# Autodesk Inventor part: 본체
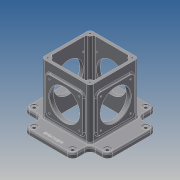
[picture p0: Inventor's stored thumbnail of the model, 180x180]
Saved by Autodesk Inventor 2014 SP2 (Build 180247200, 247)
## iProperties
Created: 2018-09
Part Number: 본체
Material: 알루미늄 6061
Document SubType Name: Modeling
Designer: mduedu
Density: 2.71 g/cm^3
Appearance: 기본값
Mass: 1126.64 g
Surface Area: 1144.86 cm^2
Volume: 415.735 cm^3
Author: mduedu
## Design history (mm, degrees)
sketch "스케치1"
  geometry: L1 (90, 52.5)-(-90, 52.5); L2 (-90, 52.5)-(-90, -52.5); L3 (-90, -52.5)-(90, -52.5); L4 (90, -52.5)-(90, 52.5); L5 (90, 52.5)-(-90, -52.5); L6 (-90, 52.5)-(90, -52.5); L7 (-52.5, -90)-(52.5, -90); L8 (52.5, -90)-(52.5, 90); L9 (52.5, 90)-(-52.5, 90); L10 (-52.5, 90)-(-52.5, -90); L11 (-52.5, -90)-(52.5, 90); L12 (52.5, -90)-(-52.5, 90); 1 further point
  constraints: 24 end point, 4 midpoint, 4 parallel, 2 horizontal, 2 perpendicular
  dimensions: "d0" = 180 distance of L3.end L2.end; "d1" = 105 distance of L2.end L1.end; "d105" = 105 distance of L9.end L8.end; "d106" = 180 distance of L8.end L7.end
extrude "돌출1" new body sketch "스케치1" distance "d2" = 10; taper "d3" = 0 deg
fillet "모깎기16" dims "d107" = 11
sketch "스케치2"
  geometry: L1 (-52.5, -52.5)-(52.5, -52.5); L2 (52.5, -52.5)-(52.5, 52.5); L3 (52.5, 52.5)-(-52.5, 52.5); L4 (-52.5, 52.5)-(-52.5, -52.5); L5 (-52.5, -52.5)-(52.5, 52.5); L6 (52.5, -52.5)-(-52.5, 52.5); 1 further point
  constraints: 12 end point, 2 midpoint, 2 parallel, 1 horizontal, 1 perpendicular
  dimensions: "d4" = 105 distance of L3.end L2.end; "d5" = 105 distance of L2.end L1.end
extrude "돌출2" join sketch "스케치2" distance "d6" = 110; taper "d7" = 0 deg
sketch "스케치14"
  geometry: L1 (-52.5, 52.5)-(52.5, 52.5) reference; L2 (52.5, 52.5)-(52.5, -52.5) reference; L3 (52.5, -52.5)-(-52.5, -52.5) reference; L4 (-52.5, -52.5)-(-52.5, 52.5) reference; L5 (46.5, 46.5)-(-46.5, 46.5); L6 (-46.5, 46.5)-(-46.5, -46.5); L7 (-46.5, -46.5)-(46.5, -46.5); L8 (46.5, -46.5)-(46.5, 46.5); 1 further point
  constraints: 8 end point, 3 other
  dimensions: "d85" = 6 distance between parallel lines of L5 L1
extrude "돌출10" cut sketch "스케치14" stored distance "d86" = 10; taper "d87" = 0 deg
fillet "모깎기1" dims "d12" = 7
sketch "스케치15"
  geometry: A1 r 7 centre (-45.5, 45.5) between (-45.5, 52.5) and (-52.5, 45.5) reference; A2 r 7 centre (45.5, 45.5) between (52.5, 45.5) and (45.5, 52.5) reference; A3 r 7 centre (45.5, -45.5) between (45.5, -52.5) and (52.5, -45.5) reference; A4 r 7 centre (-45.5, -45.5) between (-52.5, -45.5) and (-45.5, -52.5) reference; 5 further points
  constraints: 4 coincident, 4 vertical alignment, 8 other
extrude "돌출11" join sketch "스케치15" stored distance "d88" = 10; taper "d89" = 0 deg
fillet "모깎기15" dims "d90" = 3
sketch "스케치6"
  geometry: L1 (50, 20)-(130, 20); L2 (130, 20)-(130, 100); L3 (130, 100)-(50, 100); L4 (50, 100)-(50, 20); L5 (50, 20)-(130, 100); L6 (130, 20)-(50, 100); L7 (0, 0)-(180, 0) reference; 4 further points
  constraints: 12 end point, 4 midpoint, 2 parallel, 1 horizontal, 1 perpendicular, 1 vertical alignment
  dimensions: "d25" = 80 distance of L3.end L2.end; "d26" = 80 distance of L2.end L1.end; "d27" = 60 distance of point (90, 0) point (90, 60)
extrude "돌출6" join sketch "스케치6" distance "d28" = 3; taper "d29" = 0 deg
fillet "모깎기7" dims "d30" = 8
sketch "스케치7"
  geometry: C1 r 32.5 at (90, 60); 1 further point
  constraints: 1 centre point, 1 vertical alignment
  dimensions: "d32" = 65 diameter of C1; "d33" = 60 distance of C1.centre point (90, 0)
extrude "돌출7" cut sketch "스케치7" stored distance "d34" = 3; taper "d35" = 0 deg
fillet "모깎기9" dims "d36" = 3
sketch "스케치8"
  geometry: L1 (5.5, 10)-(85.5, 10); L2 (85.5, 10)-(85.5, 90); L3 (85.5, 90)-(5.5, 90); L4 (5.5, 90)-(5.5, 10); L5 (5.5, 10)-(85.5, 90); L6 (85.5, 10)-(5.5, 90); L7 (-7, -10)-(98, -10) reference; C1 r 32.5 at (45.5, 50); 4 further points
  constraints: 12 end point, 4 midpoint, 2 parallel, 1 centre point, 1 coincident, 1 horizontal, 1 perpendicular, 1 vertical alignment
  dimensions: "d37" = 80 distance of L3.end L2.end; "d38" = 80 distance of L2.end L1.end; "d39" = 60 distance from line of point (45.5, 50) L7; "d40" = 65 diameter of C1
extrude "돌출8" join sketch "스케치8" distance "d41" = 3; taper "d42" = 0 deg
fillet "모깎기10" dims "d43" = 8
extrude "돌출9" cut sketch "스케치8" stored distance "d44" = 3; taper "d45" = 0 deg
fillet "모깎기11" dims "d46" = 3
sketch "스케치9"
  geometry: L1 (50, 92)-(50, 28) reference; L2 (58, 20)-(122, 20) reference; L3 (130, 28)-(130, 92) reference; L4 (122, 100)-(58, 100) reference; C1 r 32.5 at (90, 60) reference; A1 r 8 centre (58, 92) between (58, 100) and (50, 92) reference; A2 r 8 centre (58, 28) between (50, 28) and (58, 20) reference; A3 r 8 centre (122, 28) between (122, 20) and (130, 28) reference; A4 r 8 centre (122, 92) between (130, 92) and (122, 100) reference; 5 further points
  constraints: 4 coincident
hole "구멍1" sketch "스케치9" at (58, 92), (122, 92), (122, 28), (58, 28) diameter "d47" = 3.242; stored, may be unused: countersink angle "d51" = 90 deg, drill point angle "d53" = 118 deg; dims "d48" = 6, "d49" = 4, "d50" = 2, "d52" = 9
sketch "스케치10"
  geometry: L1 (13.5, 10)-(77.5, 10) reference; L2 (85.5, 18)-(85.5, 82) reference; L3 (77.5, 90)-(13.5, 90) reference; L4 (5.5, 82)-(5.5, 18) reference; C1 r 32.5 at (45.5, 50) reference; A1 r 8 centre (13.5, 18) between (5.5, 18) and (13.5, 10) reference; A2 r 8 centre (77.5, 18) between (77.5, 10) and (85.5, 18) reference; A3 r 8 centre (77.5, 82) between (85.5, 82) and (77.5, 90) reference; A4 r 8 centre (13.5, 82) between (13.5, 90) and (5.5, 82) reference; 5 further points
  constraints: 4 coincident
hole "구멍2" sketch "스케치10" at (13.5, 82), (77.5, 82), (77.5, 18), (13.5, 18) diameter "d54" = 3.242; stored, may be unused: countersink angle "d58" = 90 deg, drill point angle "d60" = 118 deg; dims "d55" = 6, "d56" = 4, "d57" = 2, "d59" = 9
fillet "모깎기12" dims "d68" = 11
sketch "스케치16"
  geometry: A1 r 11 centre (-79, 41.5) between (-79, 52.5) and (-90, 41.5) reference; A2 r 11 centre (-79, -41.5) between (-90, -41.5) and (-79, -52.5) reference; A3 r 11 centre (79, 41.5) between (90, 41.5) and (79, 52.5) reference; A4 r 11 centre (79, -41.5) between (79, -52.5) and (90, -41.5) reference; A5 r 11 centre (-41.5, 79) between (-41.5, 90) and (-52.5, 79) reference; A6 r 11 centre (41.5, 79) between (52.5, 79) and (41.5, 90) reference; A7 r 11 centre (41.5, -79) between (41.5, -90) and (52.5, -79) reference; A8 r 11 centre (-41.5, -79) between (-52.5, -79) and (-41.5, -90) reference; 9 further points
  constraints: 8 coincident
hole "구멍5" sketch "스케치16" at (-79, 41.5), (79, 41.5), (79, -41.5), (-79, -41.5), (41.5, 79), (-41.5, 79), (-41.5, -79), (41.5, -79) diameter "d91" = 6.6; stored, may be unused: countersink angle "d95" = 90 deg, drill point angle "d97" = 118 deg; dims "d92" = 6, "d93" = 15, "d94" = 2, "d96" = 8
fillet "모깎기13" dims "d77" = 3
chamfer "모따기1" distance "d79" = 1; stored, may be unused: second distance "d80" = 2, angle "d81" = 45 deg
sketch "스케치17"
  geometry: A1 r 7 centre (-45.5, 45.5) between (-45.5, 52.5) and (-52.5, 45.5) reference; A2 r 7 centre (-45.5, -45.5) between (-52.5, -45.5) and (-45.5, -52.5) reference; A3 r 7 centre (45.5, -45.5) between (45.5, -52.5) and (52.5, -45.5) reference; A4 r 7 centre (45.5, 45.5) between (52.5, 45.5) and (45.5, 52.5) reference; 5 further points
  constraints: 4 coincident
hole "구멍6" sketch "스케치17" at (-45.5, 45.5), (45.5, 45.5), (45.5, -45.5), (-45.5, -45.5) diameter "d98" = 3.242; stored, may be unused: countersink angle "d102" = 90 deg, drill point angle "d104" = 118 deg; dims "d99" = 8, "d100" = 15, "d101" = 2, "d103" = 10
sketch "스케치13"
  geometry: L1 (90, -41.5)-(90, 41.5) reference; 2 further points
  constraints: 1 horizontal alignment, 1 other
  dimensions: "d82" = 11 distance from line of point (79, 0) L1
feature "엠보싱1" sketch "스케치13" dims "d0" = 180, "d1" = 105, "d83" = 0.5, "d84" = 0
node "솔리드1"
mirror "대칭1"
mirror "대칭4"
mirror "대칭2"
mirror "대칭5"
node "투영된 루프2"
node "투영된 루프3"
node "투영된 루프6"
